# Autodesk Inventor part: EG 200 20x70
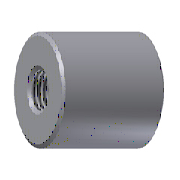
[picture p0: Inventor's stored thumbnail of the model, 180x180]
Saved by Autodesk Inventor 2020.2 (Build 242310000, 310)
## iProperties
IsCustomPart: 0
Manager: www.cadconsulting.pl
Company: Fabian Stasiak CAD Consulting
Created: 2014-02
Part Number: EG 200 20x70
Material: DIN 1.7131
Description: Locating sleeves
Document SubType Name: Modeling
Designer: F.Stasiak
Standard Revision: 1
Manufacturer: DME
Language: pl-PL
Size Designation: 20x70
Categories: <MemberInstance><Categories><Category DisplayName="Forma wtryskowa" InternalName="349578f2-f4d4-4954-8c09-8e99297a61c0" Mnemonic="MOLD"><Category DisplayName="E
Mass: 1.68626 g
Surface Area: 16.3679 cm^2
Volume: 1.68626 cm^3
Density: 7.85 g/cm^3
Appearance: Stal
Catalog Web Link: www.expertbooks.pl
Author: F.Stasiak
Subject: Zbiór ćwiczeń. Autodesk Inventor 2020. Kurs Professional
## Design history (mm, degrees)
sketch "Sketch1"
  geometry: L1 (0, -84)-(0, 14) reference; L2 (0, 0)-(10, 0); L3 (10, 0)-(10, -2.5); L4 (10, -2.5)-(9.99, -2.5); L5 (9.99, -2.5)-(9.99, -70); L6 (9.99, -70)-(8, -70); L7 (8, -70)-(8, -13); L8 (8, -13)-(4, -11); L9 (4, -11)-(0, -11); L10 (0, 0)-(0, -11); 1 further point
  constraints: 18 end point, 4 parallel, 3 perpendicular, 2 point on line, 1 coincident, 1 collinear
  dimensions: "d0" = 20 diameter of L3 L1 (= D); "d2" = 20 dimension on L5 L1 (= D_Guide); "d4" = 70 distance between parallel lines of L6 L2 (= L); "d5" = 16 diameter of L7 L1 (= d_); "d6" = 13 distance from line of L7.end L2 (= L1); "d7" = 2 distance from line of L7.end L9; "d8" = 8 diameter of L8.end L1 (= M); "d33" = 2.5 distance between parallel lines of L2 L4 (= L2)
revolve "Revolution1" sketch "Sketch1" stored, may be unused: angle "d9" = 90 deg
sketch "Sketch2"
  geometry: 1 further point
hole "Hole1" sketch "Sketch2" at (0, 0) diameter "d10" = 6.647; stored, may be unused: countersink angle "d14" = 90 deg, drill point angle "d16" = 0 deg; dims "d11" = 6, "d12" = 4, "d13" = 2, "d15" = 70 (= L)
chamfer "Chamfer1" distance "d17" = 0.5; stored, may be unused: second distance "d18" = 2, angle "d19" = 45 deg
fillet "Fillet1" dims "d30" = 0.5
body "Solid1"
other parameters: "D" = 20 [user parameter; used in 1 equation term], "L" = 70 [user parameter; used in 2 equation terms], "d_" = 16 [user parameter; used in 1 equation term], "M" = 8 [user parameter; used in 1 equation term], "L1" = 13 [user parameter; used in 1 equation term], "d22" = 0, "d31" = 0, "d32" = 0, "L2" = 2.5 [user parameter; used in 1 equation term]
